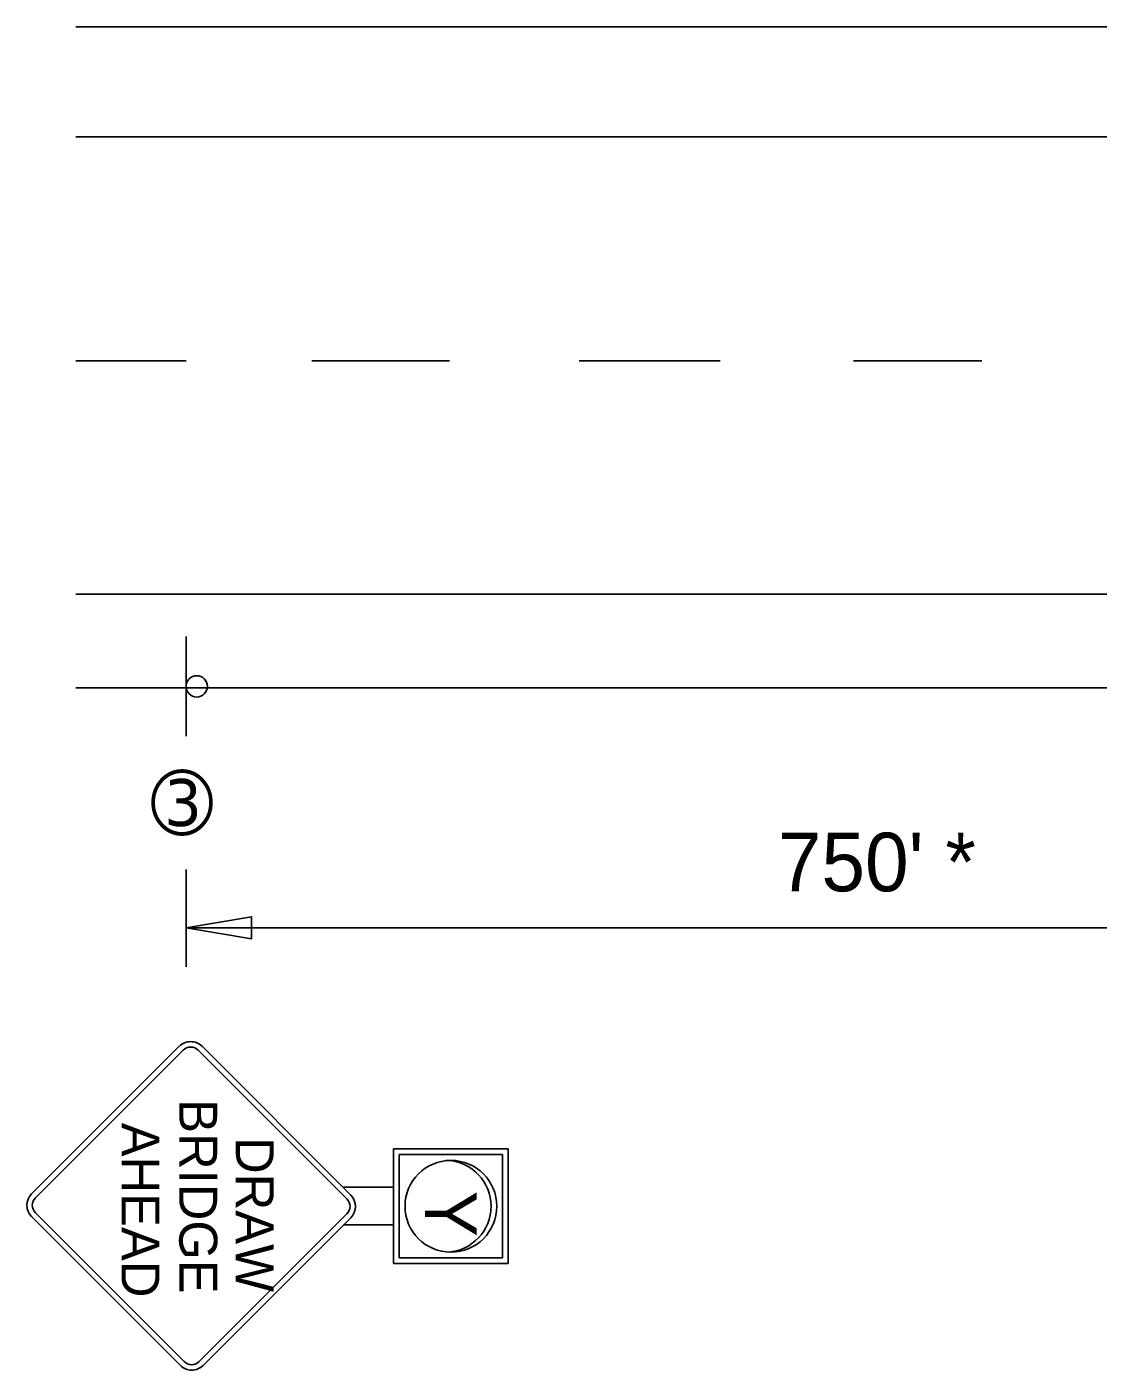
# Model space of a CAD drawing. Extents: x 10000 to 10825, y 10000 to 10530.
# Drawn here: x 10046.6 to 10110.6, y 10364 to 10444.3 of the extents above; entities that cross this region are included whole.
import ezdxf

# ---------------------------------------------------------------- set-up
doc = ezdxf.new("R2010")
doc.units = 0
for name, color, linetype in [('Default', 7, 'Continuous'), ('Dimension', 7, 'Continuous'), ('TextStructures', 7, 'Continuous')]:
    doc.layers.add(name, color=color, linetype=linetype)

msp = doc.modelspace()

# ---------------------------------------------------------------- linework, layer by layer
at = {"layer": 'Default'}
for p, q in [((10049.563, 10444.263), (10394.364, 10444.263)), ((10049.563, 10437.701), (10394.364, 10437.701)), ((10049.563, 10424.324), (10056.135, 10424.324)), ((10063.651, 10424.324), (10071.869, 10424.324)), ((10079.611, 10424.324), (10088.032, 10424.324)), ((10095.978, 10424.324), (10103.653, 10424.324)), ((10049.563, 10410.382), (10394.364, 10410.382)), ((10056.137, 10407.85), (10056.137, 10401.905)), ((10049.563, 10404.79), (10394.364, 10404.79)), ((10056.146, 10393.947), (10056.146, 10388.13)), ((10056.146, 10390.462), (10142.044, 10390.462)), ((10046.915, 10374.564), (10055.735, 10383.38)), ((10047.143, 10374.336), (10055.964, 10383.152)), ((10056.862, 10383.152), (10065.744, 10374.265)), ((10057.09, 10383.38), (10065.973, 10374.494)), ((10068.525, 10377.253), (10068.525, 10370.402)), ((10075.376, 10377.253), (10068.525, 10377.253)), ((10068.868, 10376.91), (10068.868, 10370.745)), ((10075.033, 10376.91), (10068.868, 10376.91)), ((10075.033, 10370.745), (10075.033, 10376.91)), ((10075.376, 10370.402), (10075.376, 10377.253)), ((10065.491, 10374.975), (10068.516, 10374.975)), ((10047.143, 10373.437), (10056.025, 10364.551)), ((10056.923, 10364.551), (10065.743, 10373.367)), ((10046.915, 10373.209), (10055.796, 10364.323)), ((10057.151, 10364.323), (10065.972, 10373.138)), ((10065.543, 10372.711), (10068.516, 10372.711)), ((10068.525, 10370.402), (10075.376, 10370.402)), ((10068.868, 10370.745), (10075.033, 10370.745))]:
    msp.add_line(p, q, dxfattribs=at)
for centre, radius in [((10056.774, 10404.877), 0.637), ((10071.95, 10373.827), 2.74)]:
    msp.add_circle(centre, radius, dxfattribs=at)
for centre, radius, start, end in [((10056.413, 10382.703), 0.958, 44.98473, 134.98571), ((10056.413, 10382.703), 0.635, 44.98473, 134.98571), ((10071.608, 10373.827), 2.74, 273.58332, 86.41668), ((10047.592, 10373.886), 0.958, 134.98573, 224.98455), ((10047.592, 10373.886), 0.635, 134.98573, 224.98455), ((10065.294, 10373.816), 0.635, 314.98524, 44.9843), ((10065.294, 10373.816), 0.958, 314.98524, 44.9843), ((10056.473, 10365), 0.635, 224.98483, 314.9852), ((10056.473, 10365), 0.958, 224.98483, 314.9852)]:
    msp.add_arc(centre, radius, start, end, dxfattribs=at)
at = {"layer": 'Dimension'}
msp.add_lwpolyline([(10056.146, 10390.462), (10060.051, 10389.8), (10060.051, 10391.123)], close=True, dxfattribs=at)

# ---------------------------------------------------------------- texts
at = {"layer": 'Default'}
for s, height, p in [('BRIDGE', 2.2646, (10055.734, 10380.223)), ('AHEAD', 2.2646, (10052.286, 10378.817)), ('DRAW', 2.2646, (10059.107, 10377.963)), ('Y', 3.083, (10070.409, 10374.752))]:
    msp.add_text(s, height=height, rotation=270, dxfattribs=at).set_placement(p)
at = {"layer": 'TextStructures'}
msp.add_text('➂', height=3.5, dxfattribs=at).set_placement((10054.046, 10396.193))
msp.add_text("750' *", height=3.5, rotation=0.00072, dxfattribs=at).set_placement((10091.466, 10392.636))

doc.saveas('drawing.dxf')
